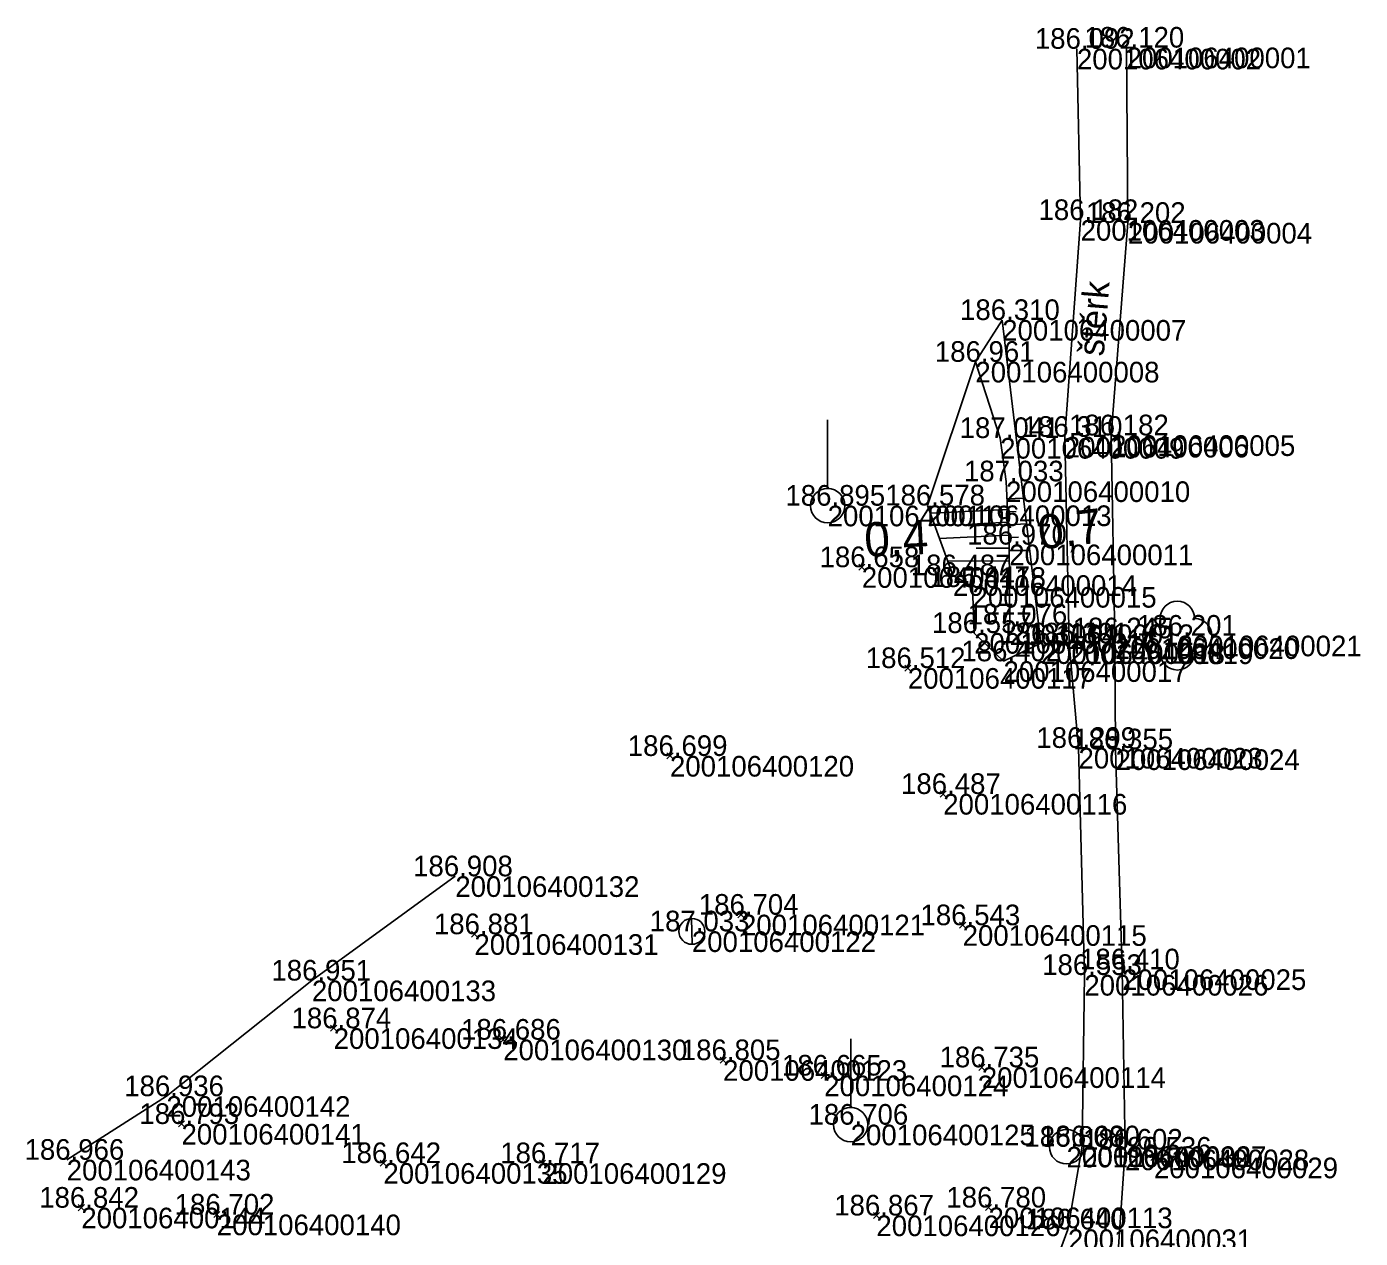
# Model space of a CAD drawing. Extents: x -601392 to -601237, y -1181159 to -1180628.
# Drawn here: x -601392.3 to -601314.7, y -1180963.1 to -1180892.7 of the extents above; entities that cross this region are included whole.
import ezdxf

# ---------------------------------------------------------------- set-up
doc = ezdxf.new("R2010")
doc.units = 0
for name, color, linetype in [('Definiční body', 7, 'Continuous'), ('OMP', 7, 'Continuous'), ('Vrstva 16', 7, 'Continuous'), ('Vrstva 37', 7, 'Continuous'), ('Vrstva 41', 7, 'Continuous'), ('Vrstva 43', 7, 'Continuous'), ('Vrstva 48', 7, 'Continuous'), ('Vrstva 49', 7, 'Continuous'), ('Vrstva 61', 7, 'Continuous')]:
    doc.layers.add(name, color=color, linetype=linetype)

msp = doc.modelspace()

# ---------------------------------------------------------------- linework, layer by layer
at = {"layer": 'Definiční body'}
msp.add_line((-601325.446, -1180928.089), (-601325.304, -1180928.089), dxfattribs=at)
for centre, start, end in [((-601325.386, -1180927.087), 0, 180), ((-601326.386, -1180928.087), 90, 270), ((-601324.386, -1180928.087), 270, 90), ((-601325.386, -1180929.087), 180, 0)]:
    msp.add_arc(centre, 1, start, end, dxfattribs=at)
at = {"layer": 'OMP'}
for p, q in [((-601331.226, -1180893.948), (-601331.226, -1180893.948)), ((-601328.335, -1180893.88), (-601328.335, -1180893.88)), ((-601331.012, -1180903.912), (-601331.012, -1180903.912)), ((-601328.258, -1180904.077), (-601328.258, -1180904.077)), ((-601335.573, -1180909.727), (-601335.573, -1180909.727)), ((-601337.134, -1180912.158), (-601337.134, -1180912.158)), ((-601335.689, -1180916.591), (-601335.689, -1180916.591)), ((-601331.929, -1180916.523), (-601331.929, -1180916.523)), ((-601329.236, -1180916.434), (-601329.236, -1180916.434)), ((-601335.346, -1180919.113), (-601335.346, -1180919.113)), ((-601345.725, -1180920.528), (-601345.725, -1180920.528)), ((-601339.921, -1180920.513), (-601339.921, -1180920.513)), ((-601335.164, -1180922.791), (-601335.164, -1180922.791)), ((-601343.74, -1180924.106), (-601343.74, -1180924.106)), ((-601338.439, -1180924.574), (-601338.439, -1180924.574)), ((-601337.301, -1180925.258), (-601337.301, -1180925.258)), ((-601335.136, -1180927.436), (-601335.136, -1180927.436)), ((-601337.204, -1180927.936), (-601337.204, -1180927.936)), ((-601329.02, -1180928.245), (-601329.02, -1180928.245)), ((-601325.375, -1180928.089), (-601325.375, -1180928.089)), ((-601333.328, -1180928.535), (-601333.328, -1180928.535)), ((-601331.669, -1180928.54), (-601331.669, -1180928.54)), ((-601335.498, -1180929.579), (-601335.498, -1180929.579)), ((-601341.059, -1180929.975), (-601341.059, -1180929.975)), ((-601354.896, -1180935.087), (-601354.896, -1180935.087)), ((-601331.134, -1180934.619), (-601331.134, -1180934.619)), ((-601328.978, -1180934.704), (-601328.978, -1180934.704)), ((-601339.004, -1180937.298), (-601339.004, -1180937.298)), ((-601367.381, -1180942.087), (-601367.381, -1180942.087)), ((-601350.766, -1180944.323), (-601350.766, -1180944.323)), ((-601353.622, -1180945.291), (-601353.622, -1180945.291)), ((-601337.874, -1180944.932), (-601337.874, -1180944.932)), ((-601366.269, -1180945.457), (-601366.269, -1180945.457)), ((-601328.595, -1180947.501), (-601328.595, -1180947.501)), ((-601375.72, -1180948.153), (-601375.72, -1180948.153)), ((-601330.796, -1180947.828), (-601330.796, -1180947.828)), ((-601374.455, -1180950.929), (-601374.455, -1180950.929)), ((-601364.593, -1180951.59), (-601364.593, -1180951.59)), ((-601351.808, -1180952.783), (-601351.808, -1180952.783)), ((-601345.925, -1180953.68), (-601345.925, -1180953.68)), ((-601336.759, -1180953.199), (-601336.759, -1180953.199)), ((-601384.185, -1180954.879), (-601384.185, -1180954.879)), ((-601383.304, -1180956.495), (-601383.304, -1180956.495)), ((-601344.386, -1180956.536), (-601344.386, -1180956.536)), ((-601331.831, -1180957.823), (-601331.831, -1180957.823)), ((-601330.916, -1180957.796), (-601330.916, -1180957.796)), ((-601328.429, -1180957.986), (-601328.429, -1180957.986)), ((-601326.748, -1180958.453), (-601326.748, -1180958.453)), ((-601389.981, -1180958.579), (-601389.981, -1180958.579)), ((-601371.565, -1180958.772), (-601371.565, -1180958.772)), ((-601362.316, -1180958.78), (-601362.316, -1180958.78)), ((-601389.132, -1180961.367), (-601389.132, -1180961.367)), ((-601336.369, -1180961.357), (-601336.369, -1180961.357)), ((-601381.254, -1180961.767), (-601381.254, -1180961.767)), ((-601342.891, -1180961.82), (-601342.891, -1180961.82)), ((-601331.747, -1180962.63), (-601331.747, -1180962.63))]:
    msp.add_line(p, q, dxfattribs=at)
at = {"layer": 'Vrstva 16'}
for points in [[(-601331.226, -1180893.948), (-601331.012, -1180903.912), (-601331.929, -1180916.523), (-601331.669, -1180928.54), (-601331.134, -1180934.619), (-601330.796, -1180947.828), (-601330.916, -1180957.796), (-601331.747, -1180962.63), (-601332.621, -1180965.006), (-601331.74, -1180971.305), (-601334.968, -1180972.44), (-601337.728, -1180973.294), (-601335.642, -1180974.623), (-601334.099, -1180975.902), (-601332.568, -1180979.738), (-601330.704, -1180989.215), (-601329.909, -1180996.728), (-601329.464, -1181005.603), (-601328.739, -1181012.985)], [(-601326.59, -1181012.666), (-601327.032, -1181006.011), (-601327.553, -1180997.241), (-601328.58, -1180988.178), (-601329.939, -1180979.963), (-601330.111, -1180975.893), (-601329.993, -1180970.217), (-601328.863, -1180964.478), (-601328.429, -1180957.986), (-601328.595, -1180947.501), (-601328.978, -1180934.704), (-601329.02, -1180928.245), (-601329.236, -1180916.434), (-601328.258, -1180904.077), (-601328.335, -1180893.88)]]:
    msp.add_lwpolyline(points, dxfattribs=at)
at = {"layer": 'Vrstva 37'}
for p, q in [((-601345.725, -1180919.528), (-601345.725, -1180915.528)), ((-601345.725, -1180920.528), (-601345.725, -1180920.528)), ((-601344.386, -1180955.536), (-601344.386, -1180951.536)), ((-601344.386, -1180956.536), (-601344.386, -1180956.536))]:
    msp.add_line(p, q, dxfattribs=at)
for centre in [(-601345.725, -1180920.528), (-601344.386, -1180956.536)]:
    msp.add_circle(centre, 1, dxfattribs=at)
at = {"layer": 'Vrstva 41'}
msp.add_line((-601353.641, -1180944.539), (-601353.603, -1180946.043), dxfattribs=at)
msp.add_circle((-601353.622, -1180945.291), 0.752, dxfattribs=at)
at = {"layer": 'Vrstva 43'}
msp.add_circle((-601331.831, -1180957.823), 1, dxfattribs=at)
at = {"layer": 'Vrstva 48'}
for p, q in [((-601335.295, -1180920.139), (-601334.336, -1180920.091)), ((-601335.265, -1180920.745), (-601339.755, -1180920.967)), ((-601335.258, -1180920.888), (-601334.752, -1180920.863)), ((-601335.228, -1180921.494), (-601337.357, -1180921.6)), ((-601335.221, -1180921.637), (-601334.158, -1180921.585)), ((-601335.191, -1180922.243), (-601339.217, -1180922.443)), ((-601335.184, -1180922.386), (-601334.626, -1180922.359)), ((-601335.163, -1180922.993), (-601337.085, -1180923.004)), ((-601335.162, -1180923.136), (-601333.973, -1180923.129)), ((-601335.158, -1180923.743), (-601338.735, -1180923.764))]:
    msp.add_line(p, q, dxfattribs=at)
at = {"layer": 'Vrstva 49'}
for p, q in [((-601343.917, -1180923.929), (-601343.563, -1180924.283)), ((-601343.917, -1180924.283), (-601343.563, -1180923.929)), ((-601341.236, -1180929.798), (-601340.882, -1180930.152)), ((-601341.236, -1180930.152), (-601340.882, -1180929.798)), ((-601355.073, -1180934.91), (-601354.719, -1180935.264)), ((-601355.073, -1180935.264), (-601354.719, -1180934.91)), ((-601339.181, -1180937.121), (-601338.827, -1180937.475)), ((-601339.181, -1180937.475), (-601338.827, -1180937.121)), ((-601350.943, -1180944.146), (-601350.589, -1180944.5)), ((-601350.943, -1180944.5), (-601350.589, -1180944.146)), ((-601366.446, -1180945.28), (-601366.092, -1180945.634)), ((-601366.446, -1180945.634), (-601366.092, -1180945.28)), ((-601338.051, -1180944.755), (-601337.697, -1180945.109)), ((-601338.051, -1180945.109), (-601337.697, -1180944.755)), ((-601374.632, -1180950.752), (-601374.278, -1180951.106)), ((-601374.632, -1180951.106), (-601374.278, -1180950.752)), ((-601364.77, -1180951.413), (-601364.416, -1180951.767)), ((-601364.77, -1180951.767), (-601364.416, -1180951.413)), ((-601351.985, -1180952.606), (-601351.631, -1180952.96)), ((-601351.985, -1180952.96), (-601351.631, -1180952.606)), ((-601336.936, -1180953.022), (-601336.582, -1180953.376)), ((-601336.936, -1180953.376), (-601336.582, -1180953.022)), ((-601346.102, -1180953.503), (-601345.748, -1180953.857)), ((-601346.102, -1180953.857), (-601345.748, -1180953.503)), ((-601383.481, -1180956.318), (-601383.127, -1180956.672)), ((-601383.481, -1180956.672), (-601383.127, -1180956.318)), ((-601326.925, -1180958.276), (-601326.571, -1180958.63)), ((-601326.925, -1180958.63), (-601326.571, -1180958.276)), ((-601371.742, -1180958.595), (-601371.388, -1180958.949)), ((-601371.742, -1180958.949), (-601371.388, -1180958.595)), ((-601362.493, -1180958.603), (-601362.139, -1180958.957)), ((-601362.493, -1180958.957), (-601362.139, -1180958.603)), ((-601389.309, -1180961.19), (-601388.955, -1180961.544)), ((-601389.309, -1180961.544), (-601388.955, -1180961.19)), ((-601381.431, -1180961.59), (-601381.077, -1180961.944)), ((-601381.431, -1180961.944), (-601381.077, -1180961.59)), ((-601336.546, -1180961.18), (-601336.192, -1180961.534)), ((-601336.546, -1180961.534), (-601336.192, -1180961.18)), ((-601343.068, -1180961.643), (-601342.714, -1180961.997)), ((-601343.068, -1180961.997), (-601342.714, -1180961.643))]:
    msp.add_line(p, q, dxfattribs=at)
for points in [[(-601339.921, -1180920.513), (-601337.134, -1180912.158), (-601335.573, -1180909.727)], [(-601335.498, -1180929.579), (-601333.328, -1180928.535), (-601335.573, -1180909.727)], [(-601337.134, -1180912.158), (-601335.689, -1180916.591), (-601335.346, -1180919.113), (-601335.164, -1180922.791), (-601335.136, -1180927.436)], [(-601339.921, -1180920.513), (-601338.439, -1180924.574), (-601337.301, -1180925.258), (-601337.204, -1180927.936), (-601335.498, -1180929.579)], [(-601389.981, -1180958.579), (-601384.185, -1180954.879), (-601375.72, -1180948.153), (-601367.381, -1180942.087)]]:
    msp.add_lwpolyline(points, dxfattribs=at)

# ---------------------------------------------------------------- texts
at = {"layer": 'OMP'}
for s, p in [('200106400002', (-601331.226, -1180895.148)), ('200106400001', (-601328.335, -1180895.08)), ('200106400003', (-601331.012, -1180905.112)), ('200106400004', (-601328.258, -1180905.277)), ('200106400007', (-601335.573, -1180910.927)), ('200106400008', (-601337.134, -1180913.358)), ('200106400009', (-601335.689, -1180917.791)), ('200106400006', (-601331.929, -1180917.723)), ('200106400005', (-601329.236, -1180917.634)), ('200106400010', (-601335.346, -1180920.313)), ('200106400119', (-601345.725, -1180921.728)), ('200106400013', (-601339.921, -1180921.713)), ('200106400011', (-601335.164, -1180923.991)), ('200106400118', (-601343.74, -1180925.306)), ('200106400014', (-601338.439, -1180925.774)), ('200106400015', (-601337.301, -1180926.458)), ('200106400012', (-601335.136, -1180928.636)), ('200106400016', (-601337.204, -1180929.136)), ('200106400020', (-601329.02, -1180929.445)), ('200106400021', (-601325.375, -1180929.289)), ('200106400018', (-601333.328, -1180929.735)), ('200106400019', (-601331.669, -1180929.74)), ('200106400017', (-601335.498, -1180930.779)), ('200106400117', (-601341.059, -1180931.175)), ('200106400120', (-601354.896, -1180936.287)), ('200106400023', (-601331.134, -1180935.819)), ('200106400024', (-601328.978, -1180935.904)), ('200106400116', (-601339.004, -1180938.498)), ('200106400132', (-601367.381, -1180943.287)), ('200106400121', (-601350.766, -1180945.523)), ('200106400122', (-601353.622, -1180946.491)), ('200106400115', (-601337.874, -1180946.132)), ('200106400131', (-601366.269, -1180946.657)), ('200106400025', (-601328.595, -1180948.701)), ('200106400133', (-601375.72, -1180949.353)), ('200106400026', (-601330.796, -1180949.028)), ('200106400134', (-601374.455, -1180952.129)), ('200106400130', (-601364.593, -1180952.79)), ('200106400123', (-601351.808, -1180953.983)), ('200106400124', (-601345.925, -1180954.88)), ('200106400114', (-601336.759, -1180954.399)), ('200106400142', (-601384.185, -1180956.079)), ('200106400141', (-601383.304, -1180957.695)), ('200106400125', (-601344.386, -1180957.736)), ('200106400030', (-601331.831, -1180959.023)), ('200106400027', (-601330.916, -1180958.996)), ('200106400028', (-601328.429, -1180959.186)), ('200106400029', (-601326.748, -1180959.653)), ('200106400143', (-601389.981, -1180959.779)), ('200106400135', (-601371.565, -1180959.972)), ('200106400129', (-601362.316, -1180959.98)), ('200106400144', (-601389.132, -1180962.567)), ('200106400113', (-601336.369, -1180962.557)), ('200106400140', (-601381.254, -1180962.967)), ('200106400126', (-601342.891, -1180963.02)), ('200106400031', (-601331.747, -1180963.83))]:
    msp.add_text(s, height=1.2, dxfattribs=at).set_placement(p)
at = {"layer": 'Vrstva 16'}
msp.add_text('štěrk', height=1.5, rotation=85.47473, dxfattribs=at).set_placement((-601329.671, -1180911.863))
at = {"layer": 'Vrstva 48'}
for s, rotation, p in [('0,7', 6.80685, (-601333.369, -1180923.091)), ('0,4', 2.83288, (-601343.545, -1180923.513))]:
    msp.add_text(s, height=2, rotation=rotation, dxfattribs=at).set_placement(p)
at = {"layer": 'Vrstva 61'}
for s, p in [('186.092', (-601333.674, -1180893.948)), ('186.120', (-601330.786, -1180893.88)), ('186.182', (-601333.46, -1180903.912)), ('186.202', (-601330.706, -1180904.077)), ('186.310', (-601338.024, -1180909.727)), ('186.961', (-601339.491, -1180912.158)), ('187.041', (-601338.046, -1180916.591)), ('186.310', (-601334.38, -1180916.523)), ('186.182', (-601331.684, -1180916.434)), ('187.033', (-601337.798, -1180919.113)), ('186.895', (-601348.181, -1180920.528)), ('186.578', (-601342.375, -1180920.513)), ('186.970', (-601337.615, -1180922.791)), ('186.658', (-601346.194, -1180924.106)), ('186.487', (-601340.891, -1180924.574)), ('186.447', (-601339.753, -1180925.258)), ('186.557', (-601339.656, -1180927.936)), ('187.076', (-601337.588, -1180927.436)), ('186.311', (-601335.685, -1180928.535)), ('186.301', (-601334.026, -1180928.54)), ('186.245', (-601331.476, -1180928.245)), ('186.201', (-601327.732, -1180928.089)), ('186.512', (-601343.507, -1180929.975)), ('186.402', (-601337.946, -1180929.579)), ('186.299', (-601333.588, -1180934.619)), ('186.355', (-601331.434, -1180934.704)), ('186.699', (-601357.35, -1180935.087)), ('186.487', (-601341.456, -1180937.298)), ('186.908', (-601369.835, -1180942.087)), ('186.704', (-601353.217, -1180944.323)), ('186.543', (-601340.326, -1180944.932)), ('186.881', (-601368.626, -1180945.457)), ('187.033', (-601356.074, -1180945.291)), ('186.553', (-601333.248, -1180947.828)), ('186.410', (-601331.046, -1180947.501)), ('186.951', (-601378.077, -1180948.153)), ('186.874', (-601376.906, -1180950.929)), ('186.686', (-601367.045, -1180951.59)), ('186.805', (-601354.264, -1180952.783)), ('186.735', (-601339.215, -1180953.199)), ('186.665', (-601348.381, -1180953.68)), ('186.936', (-601386.637, -1180954.879)), ('186.793', (-601385.756, -1180956.495)), ('186.706', (-601346.838, -1180956.536)), ('186.800', (-601334.282, -1180957.823)), ('186.680', (-601333.367, -1180957.796)), ('186.602', (-601330.877, -1180957.986)), ('186.966', (-601392.433, -1180958.579)), ('186.642', (-601374.013, -1180958.772)), ('186.717', (-601364.768, -1180958.78)), ('186.536', (-601329.2, -1180958.453)), ('186.842', (-601391.58, -1180961.367)), ('186.702', (-601383.702, -1180961.767)), ('186.867', (-601345.343, -1180961.82)), ('186.780', (-601338.82, -1180961.357)), ('186.640', (-601334.198, -1180962.63))]:
    msp.add_text(s, height=1.2, dxfattribs=at).set_placement(p)

doc.saveas('drawing.dxf')
